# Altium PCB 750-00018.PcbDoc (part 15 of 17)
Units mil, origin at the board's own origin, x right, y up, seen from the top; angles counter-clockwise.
Board outline 7086.64 x 6299.21 mil, 8 copper layers (Top Layer, L2, L3, L4, L5, L6, L7, Bottom Layer), stack 60.6 mil thick; 1356 components, 1054 nets, 4851 pads, 4296 vias.
Unrouted connection lines stored in the file: 12.
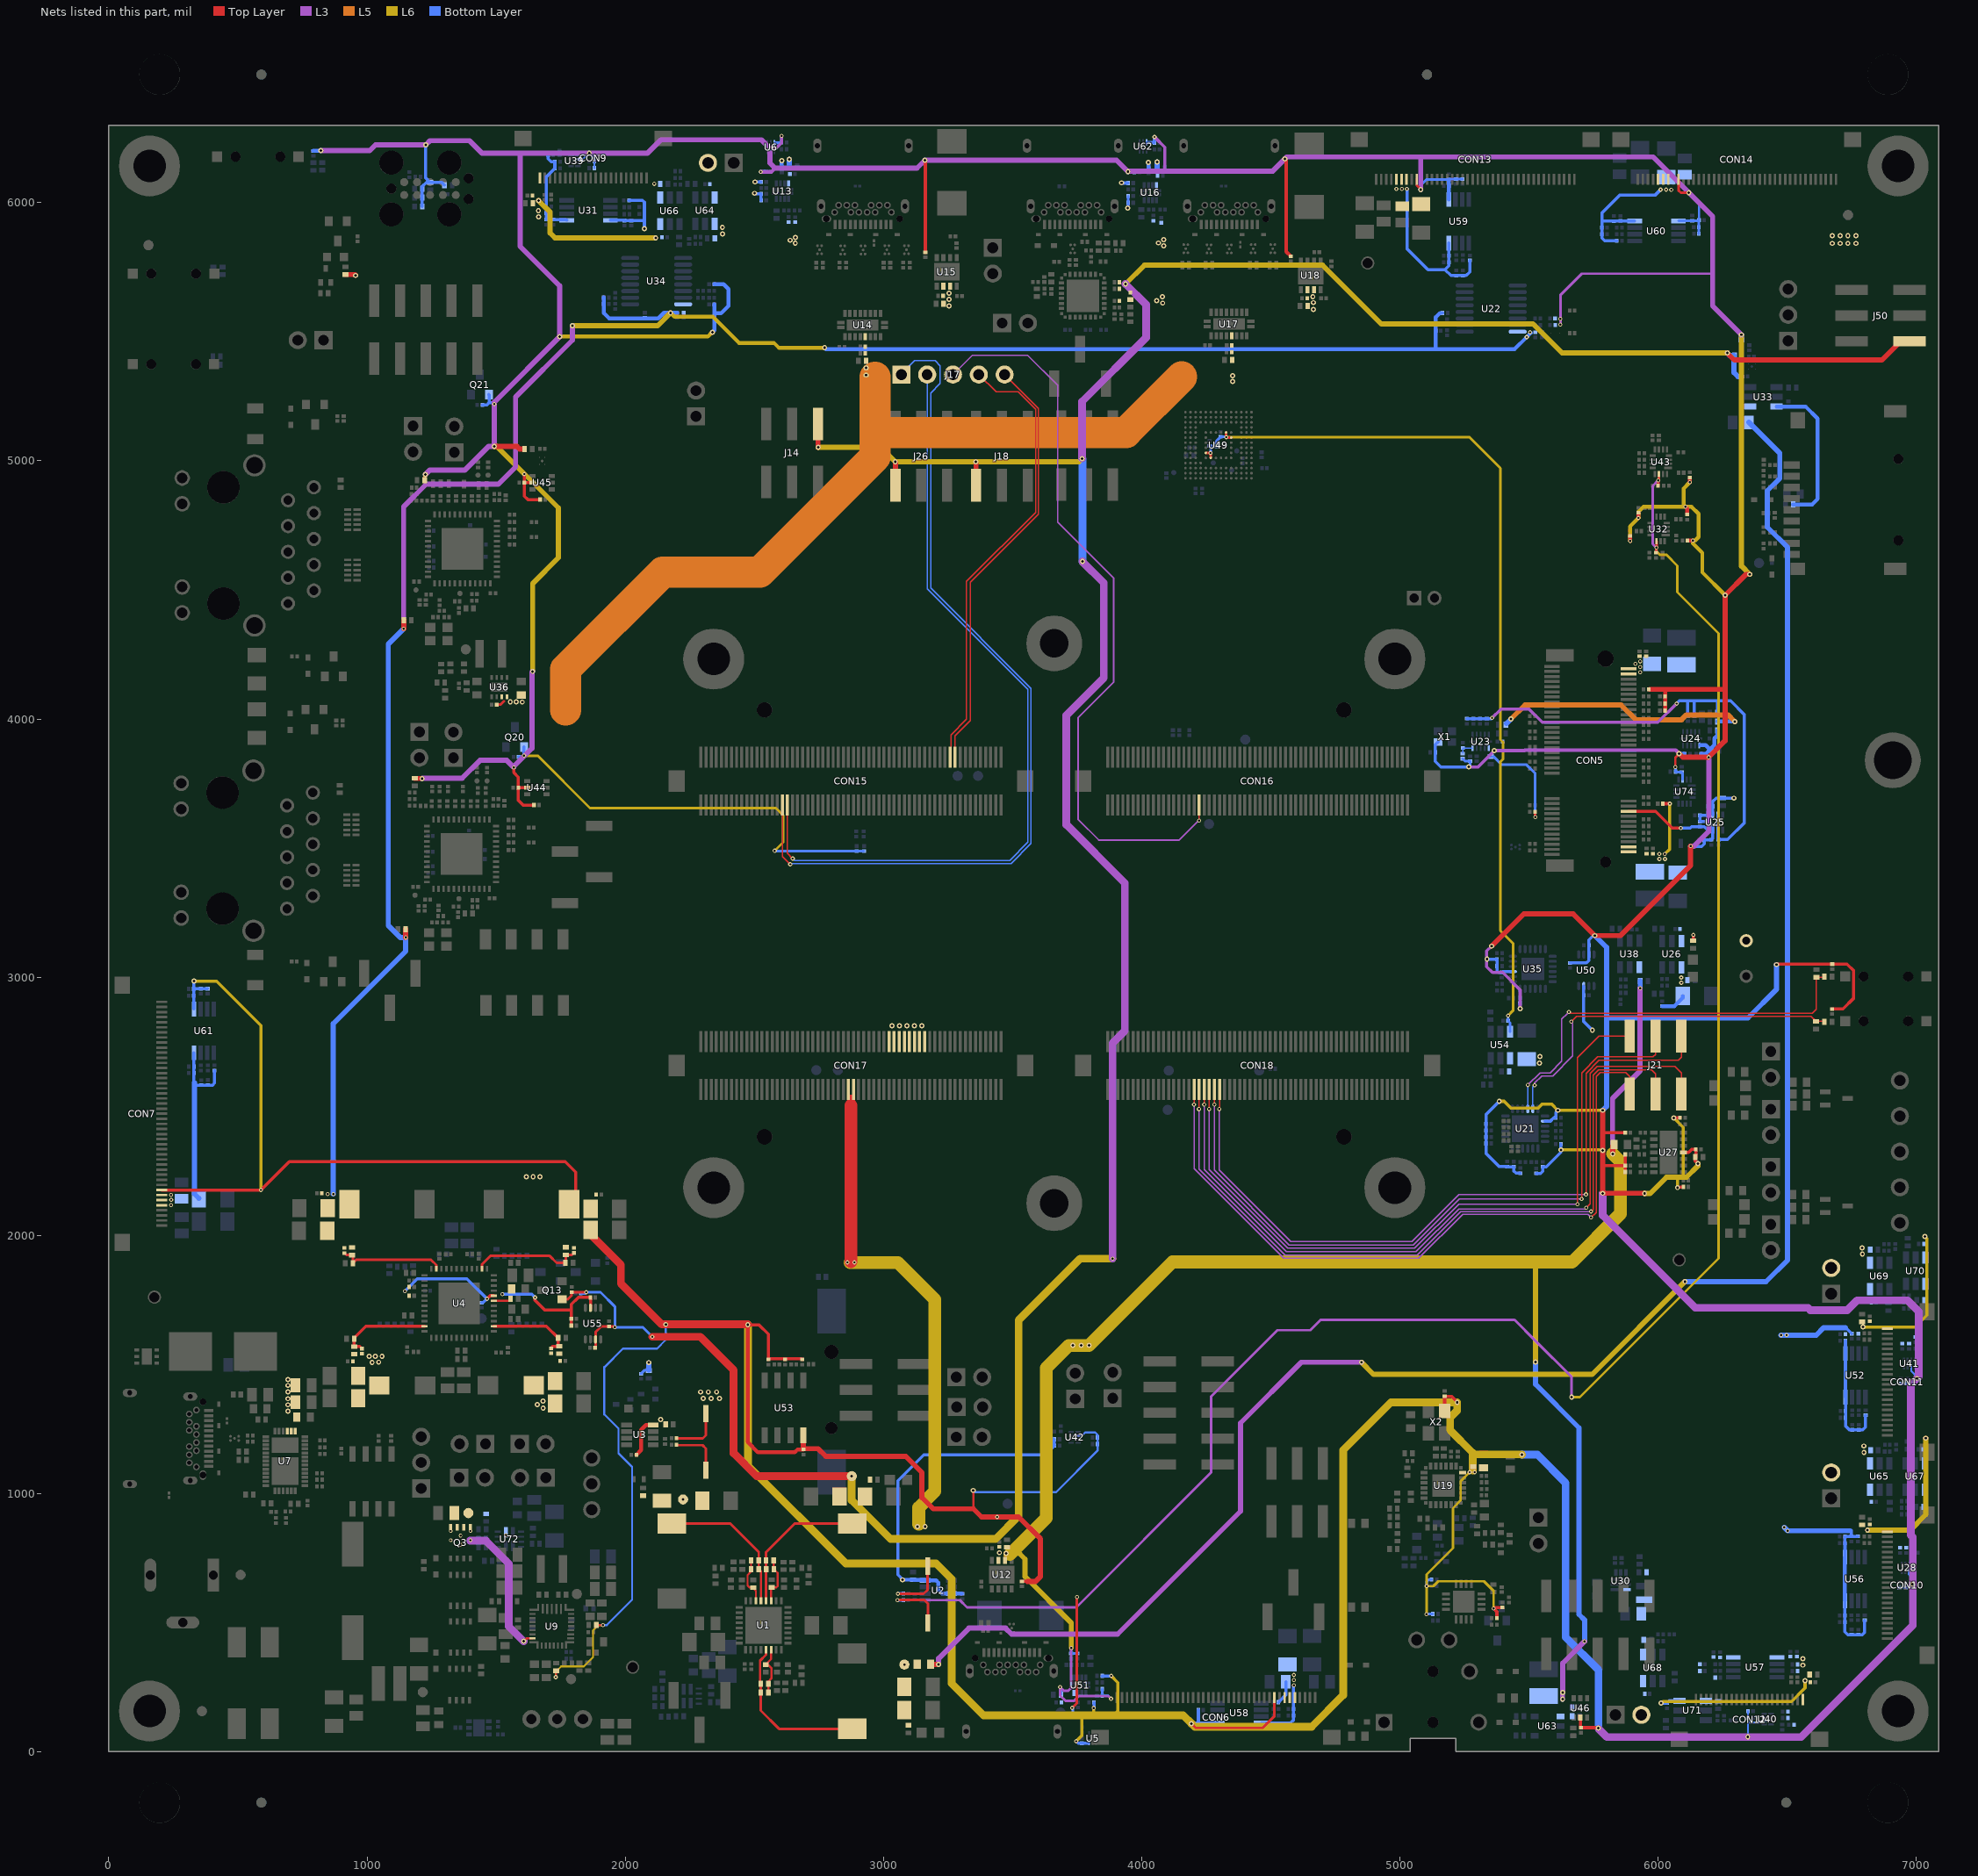
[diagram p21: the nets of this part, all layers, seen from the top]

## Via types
v1: diameter 16, hole 8, Top Layer to Bottom Layer, tented both sides, 3994 vias
v2: diameter 20, hole 10, Top Layer to Bottom Layer, tented both sides, 266 vias
v3: diameter 14, hole 7.87, Top Layer to Bottom Layer, tented both sides, 24 vias
v4: diameter 22, hole 12, Top Layer to Bottom Layer, tented both sides, 8 vias
v5: diameter 24, hole 12, Top Layer to Bottom Layer, tented both sides, 4 vias

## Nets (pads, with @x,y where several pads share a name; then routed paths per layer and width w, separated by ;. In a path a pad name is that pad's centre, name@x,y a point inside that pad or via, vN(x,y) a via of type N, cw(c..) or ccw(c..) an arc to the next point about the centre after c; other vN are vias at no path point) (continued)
VDD_1V8: C51.2 C52.1 C53.1 C58.2 C71.1 C72.1 C199.2 C200.1 C220.1 C223.1 C226.2 C232.1 C234.1 C235.2 C236.2 C255.1 C261.2 C263.1 C267.1 C268.1 C275.1 C300.1 C302.1 C320.2 C367.1 C387.1 C393.1 C405.2 C407.1 C409.2 C411.1 C413.2 C415.1 C423.1 CON6.32 CON7.38 CON13.32 CON14.32 FB2.1 FB4.1 L6.2 Q20.1 Q21.1 R38.2 R67.2 R68.2 R142.2 R151.2 R158.2 R160.1 R166.2 R173.2 R196.1 R197.1 R198.1 R202.2 R219.1 R220.1 R221.2 R222.2 R226.1 R227.1 R228.2 R229.2 R232.2 R235.2 R236.1 R279.2 R286.2 R289.1 R299.1 R303.2 R320.2 R321.2 R323.2 R324.2 R330.2 R331.2 R332.2 R333.2 R352.1 R354.2 R356.2 R361.1 R363.1 R371.2 R372.2 R375.2 R376.2 R387.2 R388.2 R389.2 R390.2 R409.1 R416.2 R420.2 R421.2 R422.2 R423.2 R427.2 R428.2 R441.2 R460.1 R461.1 R472.1 R473.1 R474.1 R491.1 R492.1 R495.1 R496.1 R500.1 R501.1 R505.1 R506.1 R515.2 R516.2 R522.2 R523.2 R530.1 R532.2 R533.1 R534.1 R535.1 R537.1 R539.2 R540.2 R541.2 R542.2 R543.2 R544.2 R545.2 R546.2 R560.2 R561.2 R570.2 R571.2 R606.2 U5.6 U6.6 U19.6 U21.8 U23.1 U24.1 U25.3 U25.5 U27.11 U28.2 U35.21 U39.2 U40.2 U41.2 U42.2 U44.5 U45.5 U46.5 U50.3 U53.8 U58.1 U59.1 U60.1 U61.1 U62.6 U74.14 X1.4 X2.4 | length 50497.5
  Top Layer w8: v1(1730.64,288.88) 1732.57,290.81 R67.2@1732.57,313.55 ; R68.2@1887.89,490.8 1913.04,490.8 v1(1913.22,490.62) ; 3345.84,939.82 3346.76,940.74 3347.68,941.66 v2(3347.68,1012.32)
  Top Layer w10: v2(4192.8,109.27) 4209.39,92.67 4468.36,92.67 4514.18,138.5 CON6.32@4514.18,209.68 ; CON13.32@5065.24,6089.26 5065.24,6067.48 5080.53,6052.19 v2(5080.53,6049.96) ; R409.1@5522.92,3640.45 5524.04,3639.33 v1(5524.04,3620.48) ; v1(6066.58,3814.19) v1(6066.58,3814.19) 6066.53,3850.83 v2(6081.55,3865.85) ; CON14.32@6078.65,6090.59 6078.65,6047.63 6087.67,6038.61 v2(6119.2,6038.61)
  Top Layer w12: CON7.38@204.84,2175.88 v1(589.38,2175.88) 698.86,2285.36 1767.66,2285.36 1807.89,2245.12 L6.2@1807.89,2124.84 ; FB4.1@1223.4,4924.29 1223.4,4944.61 v2(1226.29,4947.5) ; v1(1568.33,3812.42) 1568.33,3792.8 1585.74,3775.38 C263.1@1585.74,3734.44 ; C263.1@1585.74,3734.28 C263.1@1585.74,3734.44 ; v1@1609.32,4949.19 v1(1609.03,4948.9) C267.1@1609.03,4915.1 ; U44.5@1619.67,3734.44 C263.1@1585.74,3734.44 ; U45.5@1641.12,4915.1 C267.1@1609.03,4915.1 ; R331.2@1646.48,3666.72 1604.27,3666.72 1585.59,3685.4 1585.59,3734.33 1585.69,3734.44 C263.1@1585.74,3734.44 ; R427.2@1670.24,4849.93 1622.58,4849.93 1609.03,4863.47 C267.1@1609.03,4915.1 ; v2(2474.48,1653.79) 2517.91,1653.79 2554.1,1617.6 R472.1@2554.1,1519.14 2556.64,1521.68 2616.96,1521.68 R473.1@2619.51,1519.14 2621.91,1521.53 2682.52,1521.53 R474.1@2684.92,1519.14 ; R142.2@3536.29,660.28 3555.91,660.28 3557.18,659.02 ; X2.4@5173.24,1320.2 5173.24,1376.81 5199.69,1376.81 5221.63,1354.87 v2(5221.63,1353.44) ; R202.2@5375.55,517.41 5375.55,542.22 v1(5362.79,554.98) 5366.62,558.81 R197.1@5397.35,558.81 ; U46.5@5698.88,132.02 5699.73,131.18 5699.73,94.92 C268.1@5701.21,93.44 5766.67,93.44 v2(5767.79,92.32) ; 5785.65,2187.02 5786.43,2187.79 ; 5785.65,2269.19 5787.32,2270.85 R363.1@5872.71,2270.85 ; 5785.65,2398.43 5786.59,2397.49 R354.2@5872.71,2397.49 ; 5785.65,2452.37 5788.96,2455.67 ; R361.1@5872.71,2245.76 R363.1@5872.71,2270.85 ; R356.2@5872.71,2313.8 R363.1@5872.71,2270.85 ; v2@6060.79,2455.67 R279.2@6085.02,2455.67 ; v2(6075.11,2185.18) 6077.72,2187.79 R286.2@6097.53,2187.79 ; U27.11@6097.48,2320.97 6118.26,2320.97 6130.19,2332.89 C255.1@6145.78,2332.89 6145.78,2305.19 C220.1@6143.93,2303.34 6143.93,2287.38 v2(6153.6,2277.7) ; v2(6458.95,3048.89) 6460.76,3050.7 R533.1@6674.43,3050.7 6731.52,3050.7 6757.52,3024.7 6757.52,2918.92 6715.58,2876.98 R534.1@6673.2,2876.98
  Top Layer w15: v2(2474.48,1653.79) 2474.48,1198.97 2513,1160.46 2656.78,1160.46 2667.3,1170.98 C393.1@2689.82,1170.98 ; v2(3160.99,6164.41) 3162.21,6163.19 R158.2@3162.21,5807.51 ; v2(4554.09,6168.92) 4559.49,6163.52 4559.49,5810.03 R173.2@4576.15,5793.36 ; v1(5891.23,4689.29) R423.2@5891.23,4707.51 ; v1(5923.66,4778.63) R422.2@5923.66,4796.85 ; R299.1@6026.83,4032.19 R289.1@6026.83,4059.62 R160.1@6026.83,4087.9 6026.83,4114.79 ; v1(6105.33,4822.49) 6112.54,4815.28 R421.2@6112.54,4794.25 ; R420.2@6116.19,4690.86 v1(6134.41,4690.86) ; v1(6122.95,4916.93) R532.2@6122.95,4933.15
  Top Layer w18: FB2.1@1184.36,3770.25 1212.3,3770.25 v2(1213.08,3769.47)
  Top Layer w20: v2(1492.59,5055.38) 1581.04,5055.38 1590.6,5045.82 R537.1@1608.63,5045.82 ; C393.1@2689.85,1175.02 U53.8@2689.85,1225.9 ; C393.1@2692.55,1173.7 2746.83,1173.7 2776.59,1143.94 3086.59,1143.94 3148.74,1081.79 3148.74,984.88 3192.89,940.74 3346.76,940.74 ; 3347.68,941.66 3379.9,909.44 v1(3440.45,909.44) 3523.54,909.44 3608.08,824.9 3608.08,679.05 3588.05,659.02 3557.18,659.02 ; v2(5355.4,3120.37) 5480.08,3245.05 5670.86,3245.05 v2(5754.82,3161.09) 5854.08,3161.09 6125.77,3432.78 v1(6125.77,3507.71) ; v2(5785.32,2484.54) 5785.65,2484.22 5785.65,2452.37 5785.65,2398.43 5785.65,2329.35 v2(5785.59,2329.28) 5785.65,2329.21 5785.65,2269.19 5785.65,2187.02 5785.65,2163.16 v2(5785.57,2163.07) 5946.7,2163.07 v2(5947.55,2162.22) ; R236.1@5966.67,4114.79 6026.83,4114.79 6258.95,4114.79 ; v2(6081.55,3865.85) 6095.47,3851.93 v1(6195.35,3851.93) 6258.95,3915.53 6258.95,4114.79 ; v2@6258.95,4480.24 6258.95,4114.79 ; v2(6259.41,4479.79) 6339.84,4560.22 v2(6355.03,4560.22)
  Top Layer w30: C52.1@1866.1,2021.34 1866.1,2002.92 1982.95,1886.06 1982.95,1813.55 2141.05,1655.44 v2@2474.48,1655.44
  L3 w10: v1(5621.11,5527.65) 5621.48,5528.03 v1(5621.48,5549.79) 5621.48,5641.73 5704.63,5724.88 6211.06,5724.88
  L3 w12: 2560.42,6209.92 2583.04,6209.92 2604.85,6231.73 v1(2604.85,6258.76) ; v1(4049.44,6254.21) 4088.89,6214.75 4088.89,6122.36 ; v2(5267.01,3814.33) 5302.44,3814.33 v2(5365.96,3877.85) ; v2(5355.4,3120.37) 5336.12,3101.09 5336.12,3040.58 5358.76,3017.94 5398.21,3017.94 5465.61,2950.55 v2(5465.61,2878.64)
  L3 w15: v1(2524.52,6118.73) 2565.48,6118.73 2580.13,6133.38 ; v2(5365.96,3877.85) 5482.6,3877.85 5484.27,3879.52 6067.88,3879.52 v2(6081.55,3865.85)
  L3 w20: v2(821.09,6201.18) 1010.14,6201.18 1032.63,6223.66 v2(1227.41,6223.66) 1243.6,6239.86 1397.11,6239.86 1446.11,6190.85 v2(1860.77,6190.85) 2085.51,6190.85 ; v2(1213.08,3769.47) 1214.64,3771.03 1368.71,3771.03 1437.43,3839.75 1541,3839.75 v1(1568.33,3812.42) 1568.33,3816.27 1638.4,3886.34 1638.4,4181.57 v2(1641.28,4184.45) ; v2(1226.29,4947.5) 1243.32,4964.53 1379.39,4964.53 1470.23,5055.38 v2(1492.59,5055.38) 1492.59,5226.94 1745.51,5479.86 v2(1745.51,5481.11) 1745.51,5677.78 1592.35,5830.94 1592.35,6183.94 ; 2085.3,6190.64 2085.51,6190.85 ; v2@3947.77,6120.95 v2(3946.73,6119.91) 3902.44,6164.2 3161.2,6164.2 v2(3160.99,6164.41) 3129.96,6133.38 2580.13,6133.38 2560.42,6153.1 2560.42,6209.92 2527.07,6243.26 2137.92,6243.26 2085.51,6190.85 ; v2@3949.18,6122.36 4088.89,6122.36 4507.53,6122.36 v2(4554.09,6168.92) 4562.07,6176.9 5080.53,6176.9 ; v2(5080.53,6049.96) 5080.53,6176.9 ; v1(6125.77,3507.71) 6139.03,3507.71 6196.2,3564.88 6196.2,3851.08 v1(6195.35,3851.93) ; v2@6322.65,5488.23 6211.06,5599.82 6211.06,5724.88 6211.06,5946.74 v2(6119.2,6038.61) 5980.9,6176.9 5080.53,6176.9
  L3 w30: v2@5768.93,89.46 5801.22,57.16 6553.48,57.16 6986.03,489.71 v2(6986.03,648.51) 6986.03,831.27 6978.22,839.08 6978.22,1421.65 v2(7002.41,1445.84) 7009.68,1453.11 7009.68,1704.84 6966.16,1748.36 6770.52,1748.36 6732.61,1710.44 6589.71,1710.44 6580.87,1719.28 6143.8,1719.28 5785.57,2077.51 v2(5785.57,2163.07)
  L6 w8: v1(1730.64,288.88) 1730.64,308.93 1752.17,330.46 1838.97,330.46 1875.01,366.5 1875.01,469.74 1895.89,490.62 v1(1913.22,490.62)
  L6 w10: v1(1608,3857.8) 1660.69,3857.8 1863.42,3655.07 2583.58,3655.07 2611.44,3627.22 2611.44,3522.14 2579.04,3489.75 v1(2578.74,3489.75) ; v1@5103.37,532.77 v1(5103.37,641.6) ; v1(5270.39,1083.04) 5235.33,1047.98 5235.33,973.62 5205.36,943.65 5205.36,788.7 5103.37,686.71 v1(5103.37,641.6) ; v1(5362.79,554.98) 5362.79,622.91 5325.38,660.32 5148.23,660.32 5129.51,641.6 v1(5103.37,641.6)
  L6 w12: v2(329.52,2984.79) 417.37,2984.79 589.38,2812.77 v1(589.38,2175.88) ; v1(3746.48,40.78) 3768.47,62.77 3768.47,140.97 ; 3814.38,140.97 v1(3814.38,169.6) ; v1(3881.63,293.8) 3907.79,267.63 3907.79,158.18 3890.59,140.97 ; v2(5384.78,2519.37) 5403.62,2519.4 5429.29,2493.73 5535.62,2493.73 5549.58,2507.69 5588.5,2507.69 v2(5611.58,2484.61) 5785.26,2484.61 v2(5785.32,2484.54) ; v2(5623.15,2331.4) 5783.47,2331.4 v2(5785.59,2329.28) ; v2(6060.44,2455.32) 6097.48,2418.27 6097.48,2225.05 ; v2(6075.11,2185.18) 6075.11,2223.86 6076.3,2225.05
  L6 w15: v2(1745.51,5481.11) 2319.97,5481.11 v2(2337.19,5498.33) ; v1(5891.23,4689.29) 5891.23,4746.19 v1(5923.66,4778.63) 5923.66,4802.75 5943.4,4822.49 v1@6098.52,4822.49 ; v1(6122.95,4916.93) 6098.52,4892.5 6098.52,4829.3 v1(6105.33,4822.49) 6128.87,4822.49 6156.78,4794.58 6156.78,4704.33 6143.31,4690.86 v1(6134.41,4690.86) 6134.41,4680.27 6171.31,4643.37 6171.31,4567.88 v2@6258.95,4480.24
  L6 w20: v2(1492.59,5055.38) 1503.13,5055.38 1740.95,4817.57 1740.95,4624.72 1641.28,4525.06 v2(1641.28,4184.45) ; v2(5947.55,2162.22) 5969.42,2162.22 6032.26,2225.05 6076.3,2225.05 6097.48,2225.05 6110.07,2225.05 6153.6,2268.58 v2(6153.6,2277.7) ; v2(6322.95,5488.52) 6322.95,4592.3 v2(6355.03,4560.22)
  L6 w30: v2@2474.93,1654.25 2474.93,1108.48 2853.94,729.48 3203.09,729.48 3264.21,668.36 3264.21,264.33 3387.56,140.97 3768.47,140.97 3811.87,140.97 ; 3814.38,140.97 3890.59,140.97 4161.1,140.97 v2(4192.8,109.27) 4205.28,96.79 4657.97,96.79 4780.69,219.52 4780.69,1168.16 4965.97,1353.44 v2(5221.63,1353.44) 5221.63,1321.08 5194.43,1293.88 5194.43,1245.28 5282.2,1157.51 ; 5282.2,1088.58 5282.2,1157.51 ; v2(5472.71,1151.27) 5472.53,1151.45 5288.26,1151.45 5282.2,1157.51
  Bottom Layer w8: U39.2@1816.76,6168.66 1835.5,6168.66 1857.69,6190.85 v2(1860.77,6190.85) 1860.77,6189.34 1880.22,6169.89 1880.22,6134.16 R376.2@1880.51,6133.87 ; v1(1913.22,490.62) 1928.24,490.62 2026.46,588.84 2026.46,1102.98 1973.64,1155.8 1973.64,1251.92 1918.97,1306.59 1918.97,1489.51 1991.17,1561.71 2123.25,1561.71 2156.66,1595.12 v2(2156.66,1654.99) ; v2(3347.68,1012.32) 3354.93,1005.07 3667.95,1005.07 3829,1166.12 R523.2@3829,1191.89 R522.2@3829,1217.17 3829,1227.52 3819.81,1236.72 3780.92,1236.72 3768.72,1224.52 U42.2@3753.47,1224.52 ; v2@6347.16,57.16 6348.11,58.11 6348.11,120.43 ; R388.2@6347.93,156.78 6347.93,131.44 R387.2@6348.11,131.26 6348.11,120.43 ; U40.2@6410.66,119.69 6398.47,119.69 6391.54,112.76 6355.78,112.76 6348.11,120.43 ; R372.2@6934.29,635.5 R371.2@6959.63,635.5 6973.02,635.5 v2(6986.03,648.51) 6986.03,672.25 6971.59,686.69 U28.2@6971.59,699.7 ; R390.2@6940.39,1425.7 6965.4,1425.7 R389.2@6965.54,1425.56 6982.13,1425.56 v2(7002.41,1445.84) 7002.41,1452.15 6980.16,1474.41 U41.2@6980.16,1490.47
  Bottom Layer w10: v1(2578.74,3489.75) 2580.18,3488.32 R235.2@2895.68,3488.3 R221.2@2924.61,3488.32 ; v1(3440.45,909.44) R441.2@3462.02,909.44 ; v2(5080.53,6049.96) 5080.53,6067.83 5102.37,6089.68 C407.1@5189.1,6089.68 ; v1(5102.48,532.77) 5103.35,533.64 R198.1@5127.36,533.64 ; v1(5103.37,641.6) 5103.37,658.67 5111.88,667.17 R196.1@5122.38,667.17 ; C407.1@5190.85,6091.43 R496.1@5216.35,6091.43 R495.1@5242.33,6091.43 ; R516.2@5243.19,3846.22 5253.12,3836.29 R515.2@5271.89,3836.29 5271.89,3819.21 v2(5267.01,3814.33) ; C232.1@5352.33,3854.79 5362.42,3854.79 5394.55,3822.65 5490.44,3822.65 5524.04,3789.05 v1(5524.04,3620.48) ; v1(6066.58,3814.19) 6066.78,3813.99 R606.2@6066.78,3796.05 6068.28,3794.55 C423.1@6091.12,3794.55 6094.85,3790.81 U74.14@6094.85,3766.21 ; U60.1@6079.13,5929.32 C409.2@6131.27,5929.32 ; v2(6119.2,6038.61) 6158.5,5999.3 C411.1@6158.5,5932.14 ; C409.2@6132.17,5929.64 C411.1@6157.15,5929.64 ; R501.1@6157.45,5905 6157.45,5879.69 R500.1@6157.83,5879.31 ; R501.1@6157.78,5905.11 C411.1@6157.78,5929.61
  Bottom Layer w12: v2(329.52,2984.79) 329.52,2955.73 C415.1@328.5,2954.71 ; U61.1@329.72,2876.44 329.72,2927.73 C413.2@328.64,2928.81 328.64,2954.57 C415.1@328.5,2954.71 ; R505.1@382.43,2955.33 382.28,2955.49 R506.1@356.68,2955.49 355.9,2954.71 C415.1@328.5,2954.71 ; C300.1@1213.56,5984.85 R320.2@1213.56,6019.29 R321.2@1213.56,6053.95 1213.56,6062.04 1230.16,6078.64 R323.2@1243.79,6078.64 ; v2(1227.41,6223.66) 1226.21,6222.46 1226.21,6096.22 R323.2@1243.79,6078.64 ; R324.2@1299.82,6067.47 1288.65,6078.64 R323.2@1243.79,6078.64 ; R571.2@1446.27,5216.94 1464.05,5216.94 1472.43,5225.33 ; Q21.1@1472.03,5256.42 1472.43,5256.02 1472.43,5225.33 ; v1(1492.56,5220.35) 1487.58,5225.33 1472.43,5225.33 ; R570.2@1587.05,3852.55 1602.75,3852.55 v1(1608,3857.8) Q20.1@1608,3891.39 ; U6.6@2580.64,6230.96 2602.41,6230.96 C72.1@2604.97,6233.52 2604.97,6258.65 v1(2604.85,6258.76) ; v1(3746.48,40.78) 3754.06,33.2 C71.1@3768.26,33.2 ; C71.1@3769.08,32.38 U5.6@3793.58,32.38 ; v1(3814.38,169.6) 3815.62,170.83 R560.2@3815.62,191.07 ; R561.2@3846.99,293.84 3881.58,293.84 v1(3881.63,293.8) ; v2(3946.73,6119.91) 3946.73,6119.5 3948.5,6117.74 R166.2@3971.98,6117.74 ; U62.6@4022.1,6233.6 4046.6,6233.6 C275.1@4049.25,6230.95 4049.25,6254.02 v1(4049.44,6254.21) ; X1.4@5147.86,3910.98 5136.97,3900.09 C320.2@5136.97,3870.85 5136.97,3836.25 5158.88,3814.33 v2(5267.01,3814.33) ; v2@5337.3,3069.74 R332.2@5376.25,3069.74 5376.25,3024.16 5381.52,3018.88 C302.1@5394.49,3018.88 ; v2(5384.78,2519.37) 5333.24,2467.84 R546.2@5333.24,2432.14 R545.2@5333.24,2406.77 R544.2@5333.24,2381.4 R543.2@5333.24,2356.03 5333.24,2317.97 5385.07,2266.14 R542.2@5415.85,2266.14 5416.05,2265.94 R541.2@5441.45,2265.94 5441.45,2248.84 5449.26,2241.03 R540.2@5466.91,2241.03 ; C302.1@5399.1,3022.03 U35.21@5437.38,3022.03 ; R333.2@5464.78,2900.06 5464.78,2879.46 v2(5465.61,2878.64) ; R539.2@5527.61,2240.21 5545.25,2240.21 5553.28,2248.24 R303.2@5553.28,2265.35 5566.72,2265.35 5623.15,2321.78 v2(5623.15,2331.4) 5623.53,2331.78 R428.2@5623.53,2353.77 ; U21.8@5562.04,2442.7 5583.14,2442.7 5596.11,2455.67 C387.1@5603.71,2455.67 5603.71,2476.74 v2(5611.58,2484.61) ; R416.2@5658.23,3055.27 5722.21,3055.27 5731.74,3064.8 U50.3@5731.74,3087.95 5731.74,3123.5 C367.1@5732.3,3124.06 5732.3,3144.63 5748.76,3161.09 v2(5754.82,3161.09) ; v1(6125.77,3507.71) 6126.71,3506.77 6169.15,3506.77 6178.45,3516.07 R352.1@6178.45,3531.08 ; C235.2@6162.26,3626.53 R232.2@6162.26,3602.66 6195.56,3602.66 6211.56,3586.66 U25.3@6211.56,3570.13 6211.56,3537.17 C236.2@6206.43,3532.04 R352.1@6178.45,3532.04 ; C235.2@6164,3626.53 6190,3626.53 U25.5@6191.87,3628.4
  Bottom Layer w14: v2(4192.8,109.27) 4194.16,110.63 C223.1@4219.98,110.61 C226.2@4245.94,110.63 ; C223.1@4219.03,111.56 R492.1@4219.03,136.12 ; R492.1@4219.16,136.25 R491.1@4219.16,161.63 ; C226.2@4246.11,110.8 U58.1@4292.92,110.8
  Bottom Layer w15: R535.1@792.06,6200.36 820.27,6200.36 v2(821.09,6201.18) ; v2(2337.19,5498.33) 2344.6,5505.74 R461.1@2344.6,5605.46 R461.1@2344.76,5605.3 ; 2344.61,5571.33 2370.61,5571.33 2399.2,5599.92 2399.2,5665.57 2380.91,5683.86 R460.1@2344.6,5683.86 ; v1(2524.52,6118.73) R151.2@2542.46,6118.73 ; U59.1@5189.72,6012.35 5189.72,6065.22 C405.2@5189.98,6065.49 5189.76,6065.71 C407.1@5189.76,6087.88 ; v2(6081.55,3865.85) 6082.35,3865.05 R227.1@6101.77,3865.05 ; U24.1@6163.23,3898.68 6184.36,3898.68 C234.1@6200.87,3882.17 ; R226.1@6166.65,3865.05 6182.23,3865.05 6186.08,3861.2 ; v1(6195.35,3851.93) 6186.08,3861.2 ; R222.2@6229.52,3956.24 6229.52,3935.95 R229.2@6218.21,3924.64 6218.21,3899.51 C234.1@6200.87,3882.17 ; 6186.08,3861.2 6186.08,3867.38 C234.1@6200.87,3882.17
  Bottom Layer w20: v2(5754.82,3161.09) 5800.34,3115.56 5800.34,2842.6 ; v2(5785.32,2484.54) 5800.34,2499.56 5800.34,2842.6 ; R530.1@6322.36,5471.88 6322.36,5487.93 v2(6322.95,5488.52) ; v2(6458.95,3048.89) 6458.95,2953.85 6347.7,2842.6 5800.34,2842.6
  Bottom Layer w30: v2(5472.71,1151.27) 5531.8,1151.27 5641.8,1041.27 5641.8,443.46 5768.93,316.33 v2@5768.93,92.32
  other v1: 5289.69,1082.71
  other v2: 6347.09,57.08 5337.36,3069.8
VDD_2V5: C67.2 C68.1 C69.1 C70.2 C224.1 C227.2 C230.1 C391.2 FB15.1 FB17.1 L7.2 R44.1 R348.2 R402.2 R403.2 R466.2 R468.2 R469.2 U22.16 U34.16 | length 8379.1
  Top Layer w20: v1(1141.7,4349.37) 1142.16,4349.84 FB17.1@1142.16,4382.32 ; FB15.1@1149.02,3186.56 1149.02,3154.64 v1(1149.84,3153.82)
  L3 w20: v1(1141.7,4349.37) 1141.7,4821.89 1229.21,4909.4 1508.49,4909.4 1575.26,4976.17 1575.26,5247.25 1795.54,5467.53 v2(1795.54,5523.53)
  L6 w15: v2(2175.33,5573.36) 2190.52,5558.17 2339.16,5558.17 2440.47,5456.86 2575.66,5456.86 2594.51,5438.01 v2(2771.91,5438.01)
  L6 w20: v2(1795.54,5523.53) 2125.5,5523.53 v2(2175.33,5573.36)
  Bottom Layer w15: R469.2@1916.53,5632.35 R468.2@1916.53,5607.2 1916.53,5572.29 1937.75,5551.07 2127.35,5551.07 2149.64,5573.36 v2(2175.33,5573.36) C230.1@2201.02,5573.36 ; v2(2771.91,5438.01) 2776.95,5432.96 5138.44,5432.96 ; R348.2@5163.83,5572.68 5155.43,5572.68 5138.62,5555.87 R403.2@5138.62,5529.42 5138.62,5503.68 R402.2@5138.52,5503.58 5138.52,5433.05 5138.44,5432.96 ; v1@5506.78,5495.08 v1(5490.99,5479.29) 5444.66,5432.96 5138.44,5432.96
  Bottom Layer w20: v1(869.29,2160.01) 869.29,2820.13 1149.84,3100.69 v1(1149.84,3153.82) 1128.31,3153.82 1082.22,3199.91 1082.22,4289.9 v1(1141.7,4349.37)
  other v1: 847.34,2159.76 5504.26,5497.6
VDD_3V3: C26.1 C27.1 C43.2 C44.1 C45.1 C47.2 C74.2 C180.1 C181.2 C182.2 C189.1 C190.2 C191.2 C215.1 C216.1 C219.1 C225.2 C228.1 C229.1 C238.2 C244.1 C245.1 C301.1 C305.1 C311.1 C333.1 C334.1 C349.1 C350.1 C356.1 C368.1 C376.1 C377.1 C378.1 C379.1 C380.1 C390.2 C392.2 C394.1 C395.1 C396.2 C397.2 C398.1 C399.1 C400.2 C401.2 C402.1 C403.1 C404.2 C406.1 C408.2 C410.1 C412.2 C414.1 C416.2 CON6.34 CON6.35 CON6.36 CON7.39 CON7.40 CON7.41 CON13.34 CON13.35 CON13.36 CON14.34 CON14.35 CON14.36 L5.2 R20.2 R21.2 R26.2 R33.2 R47.2 R157.2 R172.2 R211.1 R212.1 R213.1 R214.1 R215.1 R216.1 R217.1 R218.1 R223.2 R224.2 R230.1 R233.1 R285.2 R349.2 R353.2 R359.2 R360.2 R373.2 R374.2 R377.2 R378.2 R383.2 R384.2 R385.2 R386.2 R394.1 R399.1 R400.2 R452.1 R453.1 R454.1 R455.1 R456.1 R457.1 R458.1 R459.1 R463.1 R464.1 R465.2 R481.1 R482.1 R483.2 R486.1 R487.1 R488.2 R497.2 R502.2 R507.2 R519.2 R520.1 R521.1 U2.4 U2.7 U3.4 U14.6 U17.6 U25.6 U26.1 U31.1 U31.8 U36.7 U36.8 U50.7 U52.1 U52.8 U54.1 U56.1 U56.8 U57.1 U57.8 U58.8 U59.8 U60.8 U61.8 U66.1 U67.1 U70.1 U71.1 | length 11356
  Top Layer w10: R230.1@1502.13,4055.55 1516.4,4055.55 1529.78,4068.93 ; v1(3730.54,169.93) 3749.29,188.68 v1(3749.29,598.98)
  Top Layer w15: R21.2@2042.82,1149.42 2061.64,1168.25 2061.64,1247.09 2080.29,1265.74 U3.4@2107.75,1265.74
  L5 w20: v2(5430.08,3999.92) 5484.28,4054.12 5856.93,4054.12 5913.89,3997.17 6090.68,3997.17 6109.57,4016.05 6270.67,4016.05 v2@6296.72,3990
  L5 w120: 1768.69,4035.1 1768.69,4192.68 2144.86,4568.85 2520.88,4568.85 2967.55,5015.51 2967.55,5109.8 ; 2967.55,5324.67 2967.55,5109.8 ; 4154.87,5325.18 3939.49,5109.8 2967.55,5109.8
  Bottom Layer w10: v1(3730.54,169.93) 3733.84,166.64 R47.2@3733.84,147.38
  Bottom Layer w12: 329.18,2591.54 C416.2@329.18,2628.54 C414.1@329.17,2653.91 329.72,2654.47 U61.8@329.72,2707.14 ; 331.46,2589.26 338.95,2581.78 R218.1@357.58,2581.78 357.83,2582.03 R217.1@383.39,2582.03 383.61,2581.81 401.54,2581.81 409.32,2589.6 R507.2@409.32,2638.86 ; R452.1@1693.67,5984.34 R452.1@1693.46,5984.13 ; R353.2@1701.47,6183.79 1701.47,6169.74 1713.33,6157.88 R373.2@1727.29,6157.88 R374.2@1727.29,6132.41 ; C74.2@1720.55,5934.34 1694.92,5934.34 C301.1@1694.63,5934.04 1694.63,5957.68 R453.1@1693.46,5958.85 R452.1@1693.46,5984.13 ; C74.2@1725.04,5934.34 1770.44,5934.34 U31.1@1773.32,5931.46 ; R374.2@1727.9,6133.02 R374.2@1727.29,6132.41 ; U31.8@1942.62,5931.46 1996.19,5931.46 C229.1@1997.21,5930.44 1997.34,5930.31 C390.2@2023.27,5930.31 2023.93,5930.97 2074.1,5930.97 ; R400.2@2014.4,6008.77 2066.67,6008.77 2074.1,6001.34 R399.1@2074.1,5955.97 2074.1,5930.97 ; v2(2074.1,5899.6) 2074.1,5930.97 ; v2@3075.03,666.33 3055.99,685.37 3055.99,1049.39 3156.01,1149.41 3626.32,1149.41 R521.1@3662.23,1185.32 ; R519.2@3642.68,1240.05 3642.68,1227.2 R520.1@3659.78,1210.1 ; R521.1@3661.75,1185.79 R520.1@3661.75,1210.09 ; U58.8@4462.72,111.31 4511.26,111.31 C228.1@4511.7,110.86 C225.2@4537.13,110.87 4576.29,110.87 4588.31,122.89 R212.1@4588.31,140.49 R211.1@4588.31,165.88 4588.31,256.02 v1(4589.61,257.31) ; R349.2@4529.25,191.79 4558.25,220.79 C219.1@4558.25,270.5 ; v1(5027.17,6052.41) 5027.17,5822.07 5108.75,5740.48 5174.48,5740.48 ; U59.8@5189.72,5843.05 5189.72,5794.78 C406.1@5190.13,5794.36 5190.13,5769.32 C408.2@5189.95,5769.15 5189.95,5755.96 5174.48,5740.48 ; R497.2@5270.49,5776.33 5270.49,5732.54 5271.01,5732.02 5256.41,5717.42 R213.1@5244.31,5717.42 R214.1@5218.49,5717.42 5197.54,5717.42 5174.48,5740.48 ; C368.1@5712.06,2930.16 5712.06,2827.87 v2(5745.31,2794.62) ; C368.1@5712.06,2930.16 U50.7@5712.05,2965.91 ; 5782.64,5928.64 C412.2@5828.47,5928.64 5828.56,5928.54 U60.8@5909.05,5928.54 ; R502.2@5839.95,5851.81 5792.55,5851.81 5782.42,5861.94 R215.1@5782.42,5877.28 5782.55,5877.41 R216.1@5782.55,5903.06 5782.55,5960.3 5850.65,6028.4 5987.67,6028.4 v1(6009.75,6050.47) ; C238.2@6211.53,3661.94 6211.53,3680.31 6224.96,3693.75 R233.1@6251.33,3693.75 6293.33,3693.75 v2(6293.67,3693.41) ; U25.6@6211.56,3628.4 C238.2@6211.53,3661.94 ; U56.8@6723.47,584.91 6723.47,527.46 C398.1@6723.34,527.32 C400.2@6723.39,501.88 C400.2@6723.39,501.88 6723.39,464.78 6734.92,453.25 R481.1@6775.03,453.25 6790.54,453.25 6800.12,462.84 R483.2@6800.12,509.24 ; C397.2@6723.43,807.92 C397.2@6723.43,807.92 6723.43,833.43 C399.1@6723.28,833.58 6747.82,833.58 R457.1@6748.76,834.52 ; C392.2@6724.96,1591.99 C392.2@6725.5,1591.44 ; 6724.96,1642.56 6726.3,1642.56 R455.1@6749.68,1619.19 ; U52.8@6725.5,1373.42 6725.5,1320.66 C394.1@6726,1320.16 C396.2@6726.01,1293.5 6726.01,1261.32 6740.55,1246.78 6740.68,1246.92 R464.1@6751.38,1246.92 R463.1@6777.31,1246.92 6791.78,1246.92 6802.55,1257.69 6802.55,1302.56 R465.2@6803.53,1303.54 ; 6744.53,855.95 6748.76,851.72 R457.1@6748.76,834.52 ; R456.1@6774.29,834.34 6774.12,834.52 R457.1@6748.76,834.52 ; R452.1@1693.46,5984.13 1693.46,6098.58 R374.2@1727.29,6132.41
  Bottom Layer w14: U56.1@6723.47,754.21 C397.2@6723.43,807.92 ; U52.1@6725.5,1542.72 C392.2@6725.5,1591.44
  Bottom Layer w15: R157.2@2605.96,6138.67 2605.96,6161.39 v2(2606.81,6162.25) ; v2(3074.33,665.64) 3075.03,666.33 C26.1@3115.04,666.33 3116.36,665.02 3159.84,665.02 U2.4@3161.1,663.75 3203.77,663.75 3212.73,654.79 3212.73,626.5 3226.66,612.57 U2.7@3263.47,612.57 ; U2.7@3263.69,612.34 R20.2@3304.26,612.34 ; v2(4025.78,6155.81) 4026.16,6155.43 R172.2@4026.16,6135.47 ; R26.2@6015.47,2887.89 6063,2887.89 6095.41,2920.3 C244.1@6095.41,2927.5 ; R223.2@6229.6,3990.2 6296.52,3990.2 v2(6296.91,3989.81) ; U56.8@6723.47,584.91 U56.1@6723.47,754.21 ; U52.8@6725.5,1373.42 U52.1@6725.5,1542.72
  Bottom Layer w20: 331.46,2591.54 331.46,2589.26 331.46,2160.91 C216.1@348.69,2143.68 ; R224.2@5413.2,3982.67 5430.08,3999.55 v2(5430.08,3999.92) ; v1(6476.04,1613.59) 6476.17,1613.45 6476.34,1613.63 v1(6497.45,1613.63) 6497.63,1613.45 6612.16,1613.45 6641.26,1642.56 6724.96,1642.56 ; v1(6488.22,869.59) v1(6501.87,855.95) 6744.53,855.95
  other v1: 4589.48,277.41 4589.48,297.25 240.83,2117.24 241.34,2137.61 241.02,2156.46 6089.85,2978.39 6089.39,2998.83 6050.79,6049.61 6030.63,6050.33 4986.12,6053.27 5007,6053.13 2112.6,6072.77
  other v2: 6560.82,335.49 6560.51,359.76 2136.88,1286.78 1682.05,1331.06 1658.82,1344.65 1681.18,1357.71 1616.54,2227.04 1643.2,2227.04 1670.07,2227.04 5540.88,2667.9 5541.82,2692.66 1554.81,4065.86 1578.28,4065.86 1600.79,4065.48 4351.72,5307.38 4352.22,5329.62 2932.63,5332.07 2932.71,5359.92 1664.1,5945.57 1663.59,5968.97
VDD_3V3_A: C322.2 C323.2 CON9.22 R581.2 U66.6 | length 559.9
  L6 w20: v2(1664.15,6007.38) 1708.93,5962.59 1708.93,5882.26 1727.24,5863.95 v2(2117.54,5863.95)
VDD_3V3_B: C336.2 C337.2 CON11.22 R593.2 U70.6 | length 576.7
  L6 w12: v2(6793.27,1646.07) 6795.27,1644.07 6994.5,1644.07 7041,1690.57 7041,1988.38 v2(7033.16,1996.22)
VDD_3V3_C: C324.2 C325.2 CON10.22 R582.2 U67.6 | length 546.3
  L6 w20: v2(6811.11,858.2) 6811.19,858.11 6975.85,858.11 7036.16,918.43 v2(7036.16,1214.61)
VDD_3V3_D: C338.2 C339.2 CON12.22 R594.2 U71.6 | length 684.6
  L6 w12: v2(6011.68,188.4) 6018.32,195.05 6517.24,195.05 6568.98,246.78 v2(6568.98,275.06)
  Bottom Layer w12: v2(6011.68,188.4) 6012.06,188.02 R594.2@6034.01,188.02 6043.69,197.7 U71.6@6082.38,197.7
VDD_3V3_M2: C239.2 C240.2 C241.2 C242.2 C243.1 C250.2 C251.2 C252.2 C253.2 CON5.2 CON5.4 CON5.72 CON5.74 R237.2 R239.2 R259.1 U26.6 | length 252.7
  Top Layer w12: R259.1@6018.29,3672 6044.92,3672 v1(6045.15,3672.23) ; R239.2@6135.05,3141.4 6135.87,3142.23 v1(6135.87,3163.64)
  L6 w12: v1(6025.75,3477.12) 6045.15,3496.52 v1(6045.15,3672.23)
  other v1: 6004.9,3457.69 6026.43,3457.69 6004.8,3477.02 5930.65,4180.74 5930.41,4201.61 5911.99,4213.27 5930.65,4223.09
VDD_3V3_SDIO_B: C353.1 C354.1 C355.1 R431.2 U49.E6 U49.F5 U49.J10 U49.K9 U54.6 | length 3528.2
  Top Layer w10: U49.E6@4248.09,5030.88 4266,5030.88 v1(4266.63,5030.25) 4267.77,5029.11 U49.F5@4267.77,5011.2 ; U49.J10@4326.83,5109.62 4326.83,5091.84 v1(4327.08,5091.6) 4328.74,5089.94 U49.K9@4346.51,5089.94
  L6 w10: v1(4327.08,5091.6) 5269.34,5091.6 5389.41,4971.53 5389.41,3919.86 5400.05,3909.22 5400.05,3844.96 5389.41,3834.33 5389.41,3180.21 5437.91,3131.71 5437.91,2870.06 v1(5418.54,2850.7)
  Bottom Layer w10: v1(4266.63,5030.25) 4266.63,5053.48 C354.1@4262.78,5057.33 4285.45,5057.33 C353.1@4289.77,5061.65 4289.77,5076.79 C355.1@4305.52,5092.54 4326.13,5092.54 v1(4327.08,5091.6) ; v1(5418.54,2850.7) 5418.91,2850.32 R431.2@5418.91,2830.97 5426.1,2823.78 U54.6@5426.1,2788.8
VDD_5V: C34.2 C35.1 C36.1 C41.2 C172.2 C173.1 C176.2 C177.1 C178.2 C179.1 C185.2 C186.1 C187.2 C188.1 C205.2 C206.2 C210.2 C271.2 C272.1 C321.1 FB9.2 L4.2 R28.2 R147.2 R150.2 R153.2 R154.2 R162.2 R164.2 R165.2 R168.2 R169.2 R327.2 R408.2 R417.2 R531.2 R557.2 R558.2 R562.2 R563.2 U12.2 U12.3 U13.12 U15.2 U15.3 U16.12 U18.2 U18.3 U38.1 U51.12 U63.1 | length 7428.5
  Top Layer w20: R408.2@916.86,5721.23 952.87,5721.23 v2(956.02,5718.08) ; v2@5824.92,2316.76 5824.92,2347.2 FB9.2@5829.17,2351.44
  L3 w10: v1@3727.06,402.23 3727.06,247.37 3716.39,236.71 3697.66,236.71 v1(3684.08,250.29) 3684.08,217.92 3704.15,197.85 3739.1,197.85 3757.39,216.14 3870.39,216.14 v1(3881.22,205.31)
  L3 w20: v2(5629.81,203.35) 5629.81,229.32 v2(5630.34,229.85) 5630.34,342.84 v1(5715.08,427.57) ; v2@5823.59,2316.74 5823.59,2530.74 5930.24,2637.39 v1(5930.24,2957.17)
  L6 w20: 3513.09,781.12 3547.83,746.38 3547.83,678.73 3727.17,499.38 v1(3727.17,402.35) ; 5046.41,1897.09 5047.25,1896.25 ; 5524.31,1897.09 5525.15,1896.24 v2(5525.15,1510.14)
  L6 w50: 3489.78,764.37 3630.77,905.36 3630.77,1486.72 3717.84,1573.78 v2(3733.75,1573.78) v2(3765.47,1573.78) v2(3795.66,1573.78) 4118.97,1897.09 5046.41,1897.09 5524.31,1897.09 5666.58,1897.09 5853.69,2084.21 5853.69,2285.95 v2(5823.9,2315.74)
  Bottom Layer w10: R417.2@2061.15,1464.16 2075.15,1478.17 R531.2@2091.5,1478.17 ; v1(3684.08,250.29) 3687.48,246.89 v1@3687.48,244 ; v1@3684.98,246.5 v1@3687.48,244 ; C271.2@3687.48,220.74 v1@3687.48,244 ; R557.2@3726.64,380.51 R558.2@3752.24,380.51 ; R557.2@3726.64,380.78 3726.64,401.81 v1(3727.17,402.35) ; R562.2@3846.99,242.81 R563.2@3846.99,217.24 3869.29,217.24 v1(3881.22,205.31) ; v2(3945.9,5978.36) 3947.34,5979.8 R165.2@3947.34,5999.37 R168.2@3947.34,6025.38
  Bottom Layer w12: v2(2501.19,6036.08) 2503.36,6033.9 R153.2@2526.15,6033.9 R150.2@2526.15,6008.77 ; v2(2502.5,6080.05) 2502.82,6080.37 R154.2@2526.15,6080.37
  Bottom Layer w15: v2@3922.59,6075.99 R169.2@3945.21,6075.99
  Bottom Layer w20: R531.2@2091.5,1478.17 v2(2091.5,1507.18) ; C176.2@2635.72,6140.43 v2@2635.72,6167.23 ; v2(4059.24,6157.37) 4059.45,6157.16 C185.2@4059.45,6132.67 ; v2(5525.15,1510.14) 5525.15,1423.4 5693.67,1254.88 5693.67,532.31 5715.08,510.91 v1(5715.08,427.57) ; v1@5930.13,2957.06 v1(5930.24,2957.17) 5930.49,2957.41 C321.1@5930.49,2985.85
  other v2: 3474.42,767.91 3448.75,770.87 1019.33,1508.35 1044.82,1508.86 1007.73,1531.95 1031.68,1531.95 1058.2,1531.95 4665.47,5586.13 3253.85,5599.34 4081.1,5610.8 4665.3,5612.73 4058.19,5620.69 3253.95,5625.88 4662.58,5634.9 4080.14,5635.4 3253.27,5649.09 4085.44,5832.9 2658.23,5842.61 4064.85,5843.8 2638.34,5854.14 4085.52,5856.79 2658.66,5865.25 3921.85,6076.73 2635.69,6167.26
VDD_CSI_5V: C291.2 C327.1 C328.1 C343.1 C344.1 L14.2 R572.2 U30.3 U64.1 U65.1 U68.1 U69.1
  other v2: 6797.5,1159.5 6797.11,1184.16 6790.97,1927.25 6790.59,1951.91 6674.61,5842 6704.69,5842 6734.68,5842 6766.21,5842 6674.61,5871.8 6704.69,5871.8 6734.68,5871.8 6766.21,5871.8 2377.26,5878.32 2376.03,5904.76
VDD_CSI_5V_A: J46.2 R575.2 U64.6
VDD_CSI_5V_B: J48.2 R588.2 U69.6
VDD_CSI_5V_C: J45.2 R576.2 U65.6
VDD_CSI_5V_D: J49.2 R587.2 U68.6
VDD_FB1: C41.1 R28.1 R30.2 U4.47 | length 358.5
  Top Layer w12: C41.1@980.06,1561.92 972.19,1569.8 949.51,1569.8 949.37,1569.94 949.37,1601.69 995.98,1648.3 U4.47@1222.82,1648.3
VDD_FB2: C47.1 R33.1 R35.2 U4.14 | length 336.8
  Top Layer w12: U4.14@1490.54,1648.3 1694.74,1648.3 R35.2@1739.94,1603.09 1739.94,1574.14 1743.43,1570.66 1720.25,1570.66 C47.1@1712.07,1562.47
VDD_FB3: C58.1 R38.1 R40.2 U4.26 | length 430.4
  Top Layer w10: U4.26@1445.26,1870.74 1445.26,1887.98 1477.6,1920.32 1707.52,1920.32 1734.25,1893.59 R40.2@1767.98,1893.59 1770.46,1896.06 R38.1@1770.46,1924.66 1793.99,1924.66 C58.1@1801.27,1931.94
VDD_FB4: C70.1 R44.2 R45.2 U4.35 | length 417.5
  Top Layer w10: C70.1@911.63,1931.85 919.58,1923.9 R44.2@942.65,1923.9 944.99,1921.56 R45.2@944.99,1892.72 957.42,1905.15 1248.2,1905.15 1268.1,1885.25 U4.35@1268.1,1870.74
VDD_M2_SIDEBAND: C237.2 R225.2 R444.2 R445.2 R446.2 R447.2 R448.2 R449.2 U25.2 U25.7 | length 1975.8
  L3 w12: v1(5356.98,4003.94) 5391.76,4038.72 5499.84,4038.72 5551.45,3987.11 5998.84,3987.11 v1(6071.57,4059.84)
  Bottom Layer w12: R444.2@5258.89,4001.24 R445.2@5284.73,4001.24 R446.2@5310.57,4001.24 R447.2@5336.41,4001.24 5354.28,4001.24 v1(5356.98,4003.94) ; v1(6071.57,4059.84) 6081.87,4070.14 6115.03,4070.14 ; R448.2@6114.83,4011.61 6114.83,4069.95 6115.03,4070.14 ; R449.2@6140.4,4011.64 6140.4,4068.56 6141.99,4070.14 ; R225.2@6229.28,4023.88 6229.28,4070.14 ; U25.7@6231.24,3628.4 U25.2@6231.24,3570.13 6231.24,3534.81 C237.2@6233.97,3532.09 6235.82,3533.94 6269.45,3533.94 6334.13,3598.62 6334.13,4016.36 6280.35,4070.14 6141.99,4070.14 ; 6115.03,4070.14 6141.99,4070.14
VDD_OSM_0_3V3: C10.2 C11.1 C12.1 C294.2 C295.2 L2.2 R8.1 R10.1 R18.2 R19.1 R22.2 TP2.1 U1.5 U32.14 U43.14 | length 8302.1
  Top Layer w10: U1.5@2545.11,395.25 2545.11,375.79 2522.14,352.82 2522.14,266.33 R8.1@2524.61,263.86 C10.2@2524.6,230.08 2524.6,159.63 2595.26,88.98 L2.2@2879.12,88.98 ; v1(3054.37,587.34) 3055.48,588.45 3157.92,588.45 3171.65,574.72 R22.2@3171.65,499.3 ; C294.2@5991.82,4644.07 5993.33,4645.57 v1(5993.33,4663.54) 5993.82,4664.03 U32.14@5993.82,4688.59 ; C295.2@6000.53,4903.46 v1(6000.53,4923.83) 6003.05,4926.36 U43.14@6003.05,4949.07
  L3 w10: v1(3054.37,587.34) 3295.3,587.34 3323.16,559.48 3746.88,559.48 4269.21,1081.81 4269.21,1376.38 4525.6,1632.78 4653.05,1632.78 4692.91,1672.64 5444.26,1672.64 5524.62,1592.28 5665.26,1451.64 v2(5665.26,1373.92) ; v1(5993.33,4663.54) 5979.09,4677.77 5979.09,4902.4 v1(6000.53,4923.83)
  L6 w10: v2(5665.26,1373.92) 5696.89,1373.92 6234.09,1911.12 6234.09,4331.5 6074.35,4491.24 6074.35,4593.86 6032.56,4635.64 6007.1,4635.64 5993.33,4649.42 v1(5993.33,4663.54)
  Bottom Layer w10: v1(3054.37,587.34) 3054.72,586.99 R19.1@3076.73,586.99
  other v1: 3080.83,337.64
VDD_OSM_1V8: C22.2 C23.1 C24.1 C284.1 C375.1 FB14.2 J14.1 J18.1 J26.1 J50.1 L3.2 Q13.1 R13.1 R14.1 R149.2 R290.1 R293.1 R294.1 R395.2 R437.2 R518.1 R526.1 TP3.1 U1.20 U55.3 | length 13292.1
  Top Layer w10: Q13.1@1755.66,1752.69 1777.5,1752.69 1792.39,1767.58 R518.1@1792.39,1780.49 1848.73,1780.49 v1(1849.13,1780.09) ; C375.1@1882.45,1561.92 1884.89,1564.35 U55.3@1884.89,1597.31 1884.89,1624.87 1907.4,1647.38 R437.2@1937.66,1647.38 1956.7,1647.38 v1(1959.72,1644.36) ; U1.20@2545.11,584.25 2545.11,741.48 C22.2@2545.39,741.76 2545.39,772.58 2657.24,884.43 L3.2@2879.11,884.43
  Top Layer w20: v2@2746.4,5052.73 J14.1@2746.4,5142.9 ; J26.1@3046.55,4905.44 v2@3046.55,4995.61 ; J18.1@3358.49,4905.44 v2@3358.49,4995.61 ; v2(6267.57,5417.62) 6294.96,5390.23 6866.16,5390.23 6938.23,5462.31 J50.1@6974.01,5462.31
  Top Layer w30: v1(2104.52,1607.14) 2290.78,1607.14 2419.58,1478.34 2419.58,1156.38 2508.42,1067.53 v2(2877.02,1067.53)
  L3 w30: v2(3769.01,5008.77) 3769.01,5229.15 4017.53,5477.67 4017.53,5604.53 v2(3937.36,5684.7) ; v2(3770.48,4610.03) 3853.23,4527.29 3853.23,4159.46 3708.16,4014.4 3708.16,3590.78 3934.8,3364.14 3934.8,2792.52 3886.89,2744.62 v1(3886.89,1909.74)
  L6 w20: v2(2747.23,5051.9) 2990.27,5051.9 v2(3045.72,4996.44) v2(3357.66,4996.44) 3756.68,4996.44 v2(3769.01,5008.77) ; v2(3937.36,5684.7) 4010.23,5757.56 4700.51,5757.56 4927.84,5530.23 5515.37,5530.23 5627.98,5417.62 v2(6267.57,5417.62)
  L6 w30: v2(2877.02,1067.53) 2877.02,974.22 3026.76,824.49 3435.02,824.49 3523.66,913.13 3523.66,1671.99 3761.41,1909.74 v1(3886.89,1909.74)
  Bottom Layer w10: R149.2@1827.7,1775.2 1844.24,1775.2 v1(1849.13,1780.09) 1904.05,1780.09 1959.72,1724.42 v1(1959.72,1644.36) 2067.3,1644.36 v1(2104.52,1607.14)
  Bottom Layer w20: v2(6267.57,5417.62) 6277.17,5408.02 6293.29,5408.02 6293.29,5341.81 6308.63,5326.47 R395.2@6322.31,5326.47
  Bottom Layer w30: v2(3769.01,5008.77) 3770.48,5007.31 v2(3770.48,4610.03)
VDD_OSM_S_M_5V: C5.2 C6.1 C7.1 L1.2 R2.1 R3.2 R23.2 R24.1 TP1.1 U1.21 | length 778.4
  Top Layer w10: L1.2@2180.57,884.43 2405.9,884.43 2516.89,773.43 R3.2@2516.89,741.2 C5.2@2516.89,707.62 2525.41,699.1 U1.21@2525.41,584.25 ; R24.1@2198.62,1187.4 2299.41,1187.4 2312.4,1174.42 R23.2@2312.4,1090.15
  other v2: 2223.94,977.18
VDD_SD: R318.1 R319.2 U33.6 | length 593.3
  Bottom Layer w15: U33.6@6458.49,5209.79 R319.2@6504.35,5209.79 ; R319.2@6504.35,5210.28 6570.89,5210.28 6617.49,5163.68 6617.49,4852.08 6596.6,4831.19 R318.1@6522.78,4831.19
VDD_SD_3V3: C298.1 R18.1 U33.1 | length 7586.9
  Top Layer w20: R18.1@3182.37,338.77 v2(3213.59,338.77) v2@3213.73,338.91
  L3 w20: v2(3213.59,338.77) 3213.59,361.58 3330.99,478.99 3472.8,478.99 3496.3,455.49 3906.91,455.49 4382.72,931.3 4382.72,1273.06 4618.29,1508.63 v2(4851.01,1508.63)
  L6 w20: v2(4851.01,1508.63) 4898.09,1461.56 5744.24,1461.56 v2(6104.1,1821.41)
  Bottom Layer w20: v2(6104.1,1821.41) 6104.85,1820.65 6417.96,1820.65 6501.45,1904.14 6501.45,4664.88 6423.07,4743.27 6423.07,4883.84 6471.12,4931.9 6471.12,5029.59 C298.1@6351.81,5148.9
VDDA: C55.1 U4.19 | length 67.8
  Top Layer w10: U4.19@1490.54,1746.73 1548.46,1746.73 C55.1@1555.42,1753.69
VDDD: C54.2 C374.1 R32.1 R36.1 R143.2 R435.2 R436.2 U4.20 U55.7 | length 934.3
  Top Layer w8: R36.1@1162.62,1800.37 R36.1@1162.77,1800.22
  Top Layer w12: v1(1464.5,1754.17) 1476.74,1766.41 U4.20@1490.54,1766.41 ; v1(1650.57,1759.58) 1650.57,1748.76 1688.95,1710.37 1790.98,1710.37 ; R435.2@1790.95,1650.82 1790.98,1710.37 ; U55.7@1865.2,1719.36 1865.2,1758.81 C374.1@1864.44,1759.58 1817.86,1759.58 1790.98,1732.7 1790.98,1710.37
  Bottom Layer w12: v1(1146.42,1783.94) 1194.62,1832.15 1386.53,1832.15 v1(1464.5,1754.17) 1449.91,1739.58 R143.2@1444.01,1739.58 ; v1(1523.83,1772.12) 1638.03,1772.12 v1(1650.57,1759.58)
"VENDOR DEFINED - SIZE-0 / GPIO_V0_0": CON16.38 J17.3 | length 2906.9
  Top Layer w5: v1(4222.44,3606.13) CON16.38@4222.44,3666.88
  L3 w6: J17.3@3269.1,5334.02 3343.85,5408.77 3558.35,5408.77 3674.7,5292.41 3674.7,4762.73 3891.87,4545.57 3891.87,4143.18 3753.42,4004.74 3753.42,3611.54 3833.64,3531.32 4145.01,3531.32 4219.82,3606.13 v1(4222.44,3606.13)
"VENDOR DEFINED - SIZE-0 / GPIO_V0_1": CON15.99 J17.4 | length 1760.5
  Top Layer w5: CON15.99@3257.88,3851.92 3261.29,3855.33 3261.29,3938.71 3321.46,3998.89 3321.46,4532.51 3589.38,4800.42 3589.38,5198.77 3521.45,5266.7 3436.41,5266.7 J17.4@3369.1,5334.02
"VENDOR DEFINED - SIZE-0 / GPIO_V0_2": CON15.101 J17.5 | length 1670.3
  Top Layer w5: CON15.101@3277.56,3851.92 3277.56,3935.36 3336.82,3994.63 3336.82,4528.91 3600.46,4792.54 3600.46,5202.65 J17.5@3469.1,5334.02
"VENDOR DEFINED - SIZE-M / GPIO_VM_0": CON18.75 J21.1 | length 2866.4
  Top Layer w5: v1@4301.18,2489.92 CON18.75@4301.18,2563.83 ; v1(5720.72,2158.72) 5720.72,2627.89 5770.88,2678.05 6078.13,2678.05 6089.66,2689.58 J21.1@6089.66,2771.79
  L3 w5: v1(4300.32,2489.06) 4300.32,2252.89 4576.95,1976.26 5045.94,1976.26 5228.65,2158.97 v1@5720.47,2158.97
"VENDOR DEFINED - SIZE-M / GPIO_VM_1": CON18.77 J21.3 | length 2806
  Top Layer w4: CON18.77@4281.5,2565.4 CON18.77@4281.5,2566.97
  Top Layer w5: v1@4281.5,2507.06 CON18.77@4281.5,2565.4 ; v1(5703.88,2140.65) 5703.88,2629.67 5765.42,2691.21 5980.54,2691.21 5989.66,2700.33 J21.3@5989.66,2771.79
  L3 w5: v1(4281.31,2506.87) 4281.31,2252.69 4571.32,1962.68 5051.56,1962.68 5229.53,2140.65 v1(5703.88,2140.65)
"VENDOR DEFINED - SIZE-M / GPIO_VM_2": CON18.79 J21.5 | length 2735.6
  Top Layer w5: v1@4261.81,2489.92 CON18.79@4261.81,2563.83 ; v1(5687.38,2120.91) 5687.38,2688.23 5770.93,2771.79 J21.5@5889.66,2771.79
  L3 w5: v1(4260.95,2489.06) 4260.95,2255.18 4566.09,1950.04 5056.8,1950.04 5227.67,2120.91 v1(5687.38,2120.91)
"VENDOR DEFINED - SIZE-M / GPIO_VM_3": CON18.81 J21.2 | length 2976.8
  Top Layer w4: CON18.81@4242.13,2565.4 CON18.81@4242.13,2566.97
  Top Layer w5: v1@4242.13,2507.06 CON18.81@4242.13,2565.4 ; v1(5721.91,2107.16) 5737.09,2122.34 5737.09,2627.93 5763.83,2654.67 6064.29,2654.67 6089.66,2629.29 J21.2@6089.66,2547.38
  L3 w5: v1(4241.94,2506.87) 4241.94,2255.65 4560.66,1936.93 5062.23,1936.93 5227.83,2102.54 5717.29,2102.54 v1(5721.91,2107.16)
"VENDOR DEFINED - SIZE-M / GPIO_VM_4": CON18.83 J21.4 | length 2897.9
  Top Layer w5: v1@4222.44,2489.92 CON18.83@4222.44,2563.83 ; v1(5740,2092.83) 5748.08,2100.9 5748.08,2620.31 5768.47,2640.7 5975.29,2640.7 5989.66,2626.32 J21.4@5989.66,2547.38
  L3 w5: v1(4221.58,2489.06) 4221.58,2257.47 4555.23,1923.82 5067.66,1923.82 5235.56,2091.72 5738.9,2091.72 v1(5740,2092.83)
"VENDOR DEFINED - SIZE-M / GPIO_VM_5": CON18.85 J21.6 | length 2830.2
  Top Layer w4: CON18.85@4202.76,2565.4 CON18.85@4202.76,2566.97
  Top Layer w5: v1@4202.76,2507.06 CON18.85@4202.76,2565.4 ; v1(5740.61,2069.9) 5759.86,2089.15 5759.86,2615.74 5775.43,2631.3 5874.06,2631.3 5889.66,2615.7 J21.6@5889.66,2547.38
  L3 w5: v1(4202.57,2506.87) 4202.57,2258.6 4549.99,1911.18 5072.89,1911.18 5243.12,2081.41 5729.11,2081.41 v1(5740.61,2069.9)
"VENDOR DEFINED - SIZE-S / GPIO_VS_0": CON15.34 J17.1 | length 3417.7
  Top Layer w5: CON15.34@2608.27,3666.88 2608.27,3467.68 v1(2638.77,3437.18)
  Bottom Layer w5: v1(2638.77,3437.18) 2641.63,3440.04 3494.07,3440.04 3571.64,3517.61 3571.64,4119.02 3183.16,4507.5 3183.16,5263.08 3219.66,5299.58 3219.66,5368.27 3199.75,5388.18 3121.16,5388.18 3069.1,5336.12 J17.1@3069.1,5334.02
"VENDOR DEFINED - SIZE-S; GPIO_VS_1": CON15.36 J17.2 | length 3132.6
  Top Layer w5: CON15.36@2627.96,3666.88 2627.96,3479.96 v1(2648.45,3459.46)
  Bottom Layer w5: v1(2648.45,3459.46) 2655.88,3452.04 3489.09,3452.04 3559.64,3522.59 3559.64,4114.05 3169.1,4504.59 3169.1,5270.02 J17.2@3169.1,5334.02
VFB1: C5.1 R3.1 R4.1 U1.22 | length 185.4
  Top Layer w8: R3.1@2487.36,741.2 C5.1@2487.36,707.62 2487.36,698.16 2473.47,684.27 2473.47,644.08 2481.35,636.2 R4.1@2495.67,636.2 ; R4.1@2492.92,635.98 2505.71,623.19 U1.22@2505.71,584.25
VFB2: C10.1 R8.2 R9.1 U1.6 | length 194.4
  Top Layer w8: R9.1@2542.08,337.77 2552.43,337.77 2565.75,324.46 2565.75,284.09 2554.14,272.48 R8.2@2554.14,263.86 C10.1@2554.13,230.08 ; R9.1@2544.17,337.76 2564.81,358.4 U1.6@2564.81,395.25
VFB3: C22.1 R14.2 R15.1 U1.19 | length 184.5
  Top Layer w8: U1.19@2564.81,584.25 2564.81,633.72 R15.1@2567.58,636.5 2585.03,636.5 2590.13,641.59 2590.13,692.95 R14.2@2575.2,707.87 2575.2,741.47 C22.1@2574.92,741.76
VIO_CFG: CON5.18 R232.1 U25.4 | length 340.6
  Top Layer w12: CON5.18@5886.23,3642.84 5989.66,3642.84 6055.31,3577.18 v1(6087.81,3577.18)
  Bottom Layer w12: v1(6087.81,3577.18) 6124.55,3577.18 6130.34,3582.97 R232.1@6162.26,3582.97 6179.03,3582.97 U25.4@6191.87,3570.13
VOL_DOWN: C365.1 R414.1 U21.5 | length 1427.3
  Top Layer w5: v1(5663.35,2828.14) 5684.27,2849.07 6591.7,2849.07 C365.1@6611.91,2828.86 6642.46,2828.86 R414.1@6644.01,2827.31
  L3 w5: v1(5521.58,2581.07) 5521.58,2589.42 5549.48,2617.32 5591.47,2617.32 5668.89,2694.73 5668.89,2822.61 v1(5663.35,2828.14)
  Bottom Layer w5: U21.5@5514.79,2489.95 5514.79,2574.29 v1(5521.58,2581.07)
VOL_UP: C364.1 R413.1 U21.4 | length 1588.6
  Top Layer w5: v1(5654.32,2865.6) 5660.35,2859.57 6596.31,2859.57 6612.78,2876.04 C364.1@6612.78,3000.01 6641.88,3000.01 R413.1@6644.01,3002.13
  L3 w5: v1(5495.55,2582.55) 5542.49,2629.5 5581.98,2629.5 5626.74,2674.26 5626.74,2838.03 5647.6,2858.89 v1(5654.32,2865.6)
  Bottom Layer w5: U21.4@5495.1,2489.95 5495.1,2582.11 v1(5495.55,2582.55)
VPD_output: C84.2 C85.2 C86.2 C98.1 Q3.5 Q3.6 Q3.7 Q3.8 R600.2 TP6.1 U7.20 U7.21 U7.22 U9.8 U72.7 | length 549.7
  Top Layer w8: v2(1606.55,427.84) 1618.02,439.31 U9.8@1640.77,439.31
  L3 w30: v3@1399.55,817.46 1459.98,817.46 1548.84,728.59 1548.84,485.55 v2(1606.55,427.84)
  other v1: 1537.29,839.15
  other v2: 693.79,1319 693.59,1343.82 693.59,1367.42 693.59,1394.09 693.94,1418.75 693.3,1442.14
  other v3: 1362.13,801.66 1323.74,819.46 1400.52,819.46 1362.13,837.29 1323.74,855.09 1400.52,855.09
VSYS_3V3: CON17.59 CON17.61 R22.1 R25.1 | length 2148.8
  Top Layer w10: v1(3055.49,612.08) 3055.85,611.72 3155.59,611.72 3170.2,626.33 R22.1@3170.2,717.34
  Top Layer w30: 2874.41,2502.87 2874.41,2529.82
  Top Layer w50: 2874.41,1898.76 2874.41,2502.87
  L6 w50: 2870.67,1895.02 3055.66,1895.02 3199.14,1751.54 3199.14,1008.45 3136.89,946.2 3136.89,881.21
  Bottom Layer w10: v1(3055.49,612.08) 3056.43,613.02 R25.1@3076.91,613.02
  other v1: 2860.64,1895.22 2887.46,1895.22
  other v2: 3161.35,871.89 3130.9,872.26
VSYS_5V: CON17.32 CON17.34 CON17.36 CON17.38 CON17.40 CON17.42 CON17.44 CON17.46 R23.1 R29.1 | length 202.1
  Top Layer w10: R29.1@2199.19,1213.46 2299.9,1213.46 2312.4,1225.96 R23.1@2312.4,1309.64
  other v2: 2302.38,1368.16 2332.45,1368.16 2364.77,1368.16 2291.36,1393.22 2321.42,1393.22 2353.74,1393.22 3033.31,2811.15 3062.04,2811.15 3090.78,2811.15 3119.52,2811.15 3148.25,2811.15
XIN32: R351.2 R516.1 U23.5 | length 60.8
  Bottom Layer w5: R516.1@5243.19,3865.9 5243.57,3866.29 R351.2@5243.57,3888.29 5244.5,3887.36 U23.5@5281.43,3887.36
pads on no net: BAT1.3 BAT1.4 CON1.3 CON2.15 CON2.16 CON2.17 CON2.18 CON3.17 CON3.18 CON4.6 CON4.7 CON5.6 CON5.16 CON5.23 CON5.40 CON5.42 CON5.44 CON5.46 CON5.48 CON5.59 CON5.61 CON5.65 CON5.66 CON5.67 CON5.68 CON5.70 CON5.71 CON5.73 CON5.76 CON5.77 CON5.78 CON5.79 CON6.1 CON6.2 CON6.4 CON6.31 CON8.14 CON8.15 CON13.1 CON13.2 CON13.3 CON13.4 CON13.29 CON13.31 CON14.1 CON14.2 CON14.3 CON14.4 CON14.29 CON14.31 J1.9 J1.10 J1.A2 J1.A3 J1.A8 J1.A10 J1.A11 J1.B2 J1.B3 J1.B8 J1.B10 J1.B11 J4.9 J4.10 J4.A8 J4.B8 J5.9 J5.10 J5.A8 J5.B8 J24.0 J24.7 J24.11 J24.12 J24.13 J52.1 J52.2 MH2.1 MH3.1 MH4.1 MH5.1 MH6.1 MH7.1 MH8.1 MH9.1 MH10.1 MH11.1 MH12.1 MH13.1 MH14.1 MH15.1 P1.9 P1.10 P1.A2 P1.A3 P1.A8 P1.A10 P1.A11 P1.B2 P1.B3 P1.B8 P1.B10 P1.B11 P2.9 P2.10 P2.A2 P2.A3 P2.A8 P2.A10 P2.A11 P2.B2 P2.B3 P2.B8 P2.B10 P2.B11 S1.1 S2.3 S2.4 S3.3 S3.4 S5.3 S5.4 S6.3 S6.4 S7.4 S7.5 S8.3 S8.4 U1.1 U1.31 U1.32 U4.13 U4.27 U4.34 U4.44 U4.48 U5.5 U6.5 U9.6 U9.7 U9.12 U10.20 U10.21 U10.22 U10.23 U11.20 U11.21 U11.22 U11.23 U14.1 U14.10 U17.1 U17.10 U19.10 U19.11 U19.17 U19.18 U20.0 U21.6 U21.13 U24.4 U24.5 U24.7 U24.8 U29.5 U29.10 U29.12 U29.13 U29.21 U29.22 U29.23 U29.25 U29.27 U29.28 U29.29 U29.31 U30.1 U35.17 U49.A1 U49.A2 U49.A7 U49.A8 U49.A9 U49.A10 U49.A11 U49.A12 U49.A13 U49.A14 U49.B1 U49.B7 U49.B8 U49.B9 U49.B10 U49.B11 U49.B12 U49.B13 U49.B14 U49.C1 U49.C3 U49.C5 U49.C7 U49.C8 U49.C9 U49.C10 U49.C11 U49.C12 U49.C13 U49.C14 U49.D1 U49.D2 U49.D3 U49.D4 U49.D12 U49.D13 U49.D14 U49.E1 U49.E2 U49.E3 U49.E5 U49.E8 U49.E9 U49.E10 U49.E12 U49.E13 U49.E14 U49.F1 U49.F2 U49.F3 U49.F10 U49.F12 U49.F13 U49.F14 U49.G1 U49.G2 U49.G3 U49.G10 U49.G12 U49.G13 U49.G14 U49.H1 U49.H2 U49.H3 U49.H12 U49.H13 U49.H14 U49.J1 U49.J2 U49.J3 U49.J12 U49.J13 U49.J14 U49.K1 U49.K2 U49.K3 U49.K6 U49.K7 U49.K10 U49.K12 U49.K13 U49.K14 U49.L1 U49.L2 U49.L3 U49.L12 U49.L13 U49.L14 U49.M1 U49.M2 U49.M3 U49.M7 U49.M8 U49.M9 U49.M10 U49.M11 U49.M12 U49.M13 U49.M14 U49.N1 U49.N3 U49.N6 U49.N7 U49.N8 U49.N9 U49.N10 U49.N11 U49.N12 U49.N13 U49.N14 U49.P1 U49.P2 U49.P7 U49.P8 U49.P9 U49.P10 U49.P11 U49.P12 U49.P13 U49.P14 U62.5 X1.1 X2.1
